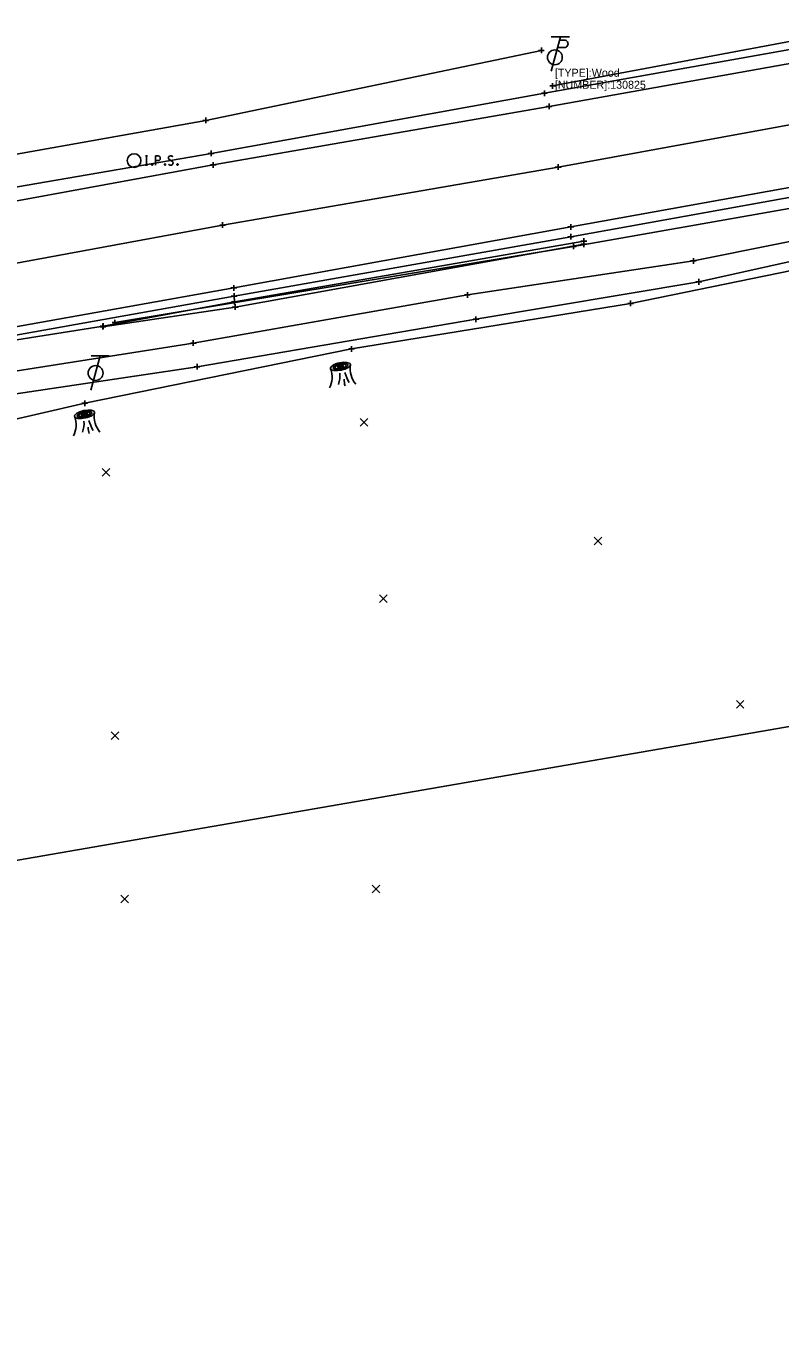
# Model space of a CAD drawing. Extents: x 1386013 to 1389776, y 604170 to 607009.
# Drawn here: x 1387481.7 to 1387613.6, y 604637.2 to 604864.4 of the extents above; entities that cross this region are included whole.
import ezdxf

# ---------------------------------------------------------------- set-up
doc = ezdxf.new("R2010")
doc.units = 0
for name, color, linetype in [('_CIVIL_CONSTRUCTION', 7, 'Continuous'), ('DV_X_Text', 7, 'Continuous'), ('PM_X_CL_Double_Solid', 7, 'Continuous'), ('PV_X_COP', 7, 'Continuous'), ('PV_X_EOP', 7, 'Continuous'), ('PV_X_Shoulder', 7, 'Continuous'), ('PV_X_Shoulder_Aggregate', 7, 'Continuous'), ('RD_X_GR_Lt', 7, 'Continuous'), ('RD_X_GR_Rt', 7, 'Continuous'), ('SC_Scratch13', 7, 'Continuous'), ('SH_Cut_Line', 7, 'Continuous'), ('SV_P_Mon_Cells_Set', 7, 'Continuous'), ('SV_X_Random_Point', 7, 'Continuous'), ('SV_X_Text', 7, 'Continuous'), ('SV_X_Toe_of_Slope', 7, 'Continuous'), ('SV_X_Top_of_Bank', 7, 'Continuous'), ('UT_X_Telecom_Cells', 7, 'Continuous')]:
    doc.layers.add(name, color=color, linetype=linetype)

msp = doc.modelspace()

# ---------------------------------------------------------------- linework, layer by layer
at = {"layer": '_CIVIL_CONSTRUCTION'}
for p, q in [((1387537.11, 604803.34), (1387537.11, 604803.34)), ((1387492.34, 604794.97), (1387492.34, 604794.97))]:
    msp.add_line(p, q, dxfattribs=at)
for centre, radius, start, end in [((1387542.72, 604804.48), 4.29, 171.4106, 219.9194), ((1387531.28, 604802.99), 4, 331.5338, 20.9269), ((1387531.6, 604803.37), 5.05, 340.7938, 3.5481), ((1387543.62, 604805.4), 6.32, 194.9653, 212.1216), ((1387541.02, 604802.54), 3.64, 178.7926, 197.1224), ((1387486.5, 604794.62), 4, 331.5338, 20.9269), ((1387497.94, 604796.11), 4.29, 171.4106, 219.9194), ((1387486.82, 604794.99), 5.05, 340.7938, 3.5481), ((1387496.24, 604794.17), 3.64, 178.7926, 197.1224), ((1387498.84, 604797.02), 6.32, 194.9653, 212.1216)]:
    msp.add_arc(centre, radius, start, end, dxfattribs=at)
for centre, major_axis in [((1387536.74, 604804.85), (1.74, 0.37)), ((1387536.74, 604804.85), (1.3, 0.28)), ((1387536.74, 604804.85), (0.976, 0.211)), ((1387536.74, 604804.85), (0.549, 0.119)), ((1387536.74, 604804.85), (0.309, 0.067)), ((1387491.96, 604796.48), (1.74, 0.37)), ((1387491.96, 604796.48), (1.3, 0.28)), ((1387491.96, 604796.48), (0.976, 0.211)), ((1387491.96, 604796.48), (0.549, 0.119)), ((1387491.96, 604796.48), (0.309, 0.067))]:
    msp.add_ellipse(centre, major_axis=major_axis, ratio=0.36865, dxfattribs=at)
at = {"layer": 'DV_X_Text'}
for p, q in [((1387571.4, 604860.13), (1387572.4, 604860.13)), ((1387571.9, 604860.63), (1387571.9, 604859.63)), ((1387571.9, 604860.13), (1387571.9, 604860.13)), ((1387572.42, 604853.14), (1387572.42, 604852.14)), ((1387573.36, 604853.92), (1387574.36, 604853.92)), ((1387573.86, 604854.42), (1387573.86, 604853.42)), ((1387573.86, 604853.92), (1387573.86, 604853.92)), ((1387571.92, 604852.64), (1387572.92, 604852.64)), ((1387572.42, 604852.64), (1387572.42, 604852.64)), ((1387573.23, 604850.83), (1387573.23, 604849.83)), ((1387513.17, 604848.4), (1387513.17, 604847.4)), ((1387572.73, 604850.33), (1387573.73, 604850.33)), ((1387573.23, 604850.33), (1387573.23, 604850.33)), ((1387512.67, 604847.9), (1387513.67, 604847.9)), ((1387513.17, 604847.9), (1387513.17, 604847.9)), ((1387513.6, 604842.11), (1387514.6, 604842.11)), ((1387514.1, 604842.61), (1387514.1, 604841.61)), ((1387514.1, 604842.11), (1387514.1, 604842.11)), ((1387513.98, 604840.1), (1387514.98, 604840.1)), ((1387514.48, 604840.6), (1387514.48, 604839.6)), ((1387514.48, 604840.1), (1387514.48, 604840.1)), ((1387574.32, 604839.73), (1387575.32, 604839.73)), ((1387574.82, 604840.23), (1387574.82, 604839.23)), ((1387574.82, 604839.73), (1387574.82, 604839.73)), ((1387516.12, 604830.08), (1387516.12, 604829.08)), ((1387515.62, 604829.58), (1387516.62, 604829.58)), ((1387516.12, 604829.58), (1387516.12, 604829.58)), ((1387576.54, 604829.26), (1387577.54, 604829.26)), ((1387577.02, 604828.03), (1387577.02, 604827.03)), ((1387577.04, 604829.76), (1387577.04, 604828.76)), ((1387577.04, 604829.26), (1387577.04, 604829.26)), ((1387576.52, 604827.53), (1387577.52, 604827.53)), ((1387577, 604825.85), (1387578, 604825.85)), ((1387577.02, 604827.53), (1387577.02, 604827.53)), ((1387577.5, 604826.35), (1387577.5, 604825.35)), ((1387577.5, 604825.85), (1387577.5, 604825.85)), ((1387578.79, 604826.22), (1387579.79, 604826.22)), ((1387578.81, 604826.78), (1387579.81, 604826.78)), ((1387579.29, 604826.72), (1387579.29, 604825.72)), ((1387579.29, 604826.22), (1387579.29, 604826.22)), ((1387579.31, 604827.28), (1387579.31, 604826.28)), ((1387579.31, 604826.78), (1387579.31, 604826.78)), ((1387597.98, 604823.3), (1387598.98, 604823.3)), ((1387598.48, 604823.8), (1387598.48, 604822.8)), ((1387598.48, 604823.3), (1387598.48, 604823.3)), ((1387518.08, 604819.08), (1387518.08, 604818.08)), ((1387598.93, 604819.65), (1387599.93, 604819.65)), ((1387599.43, 604820.15), (1387599.43, 604819.15)), ((1387599.43, 604819.65), (1387599.43, 604819.65)), ((1387517.58, 604818.58), (1387518.58, 604818.58)), ((1387517.62, 604817.16), (1387518.62, 604817.16)), ((1387518.08, 604818.58), (1387518.08, 604818.58)), ((1387518.12, 604817.66), (1387518.12, 604816.66)), ((1387518.12, 604817.16), (1387518.12, 604817.16)), ((1387518.18, 604816.66), (1387518.18, 604815.66)), ((1387558.45, 604817.37), (1387559.45, 604817.37)), ((1387558.95, 604817.87), (1387558.95, 604816.87)), ((1387558.95, 604817.37), (1387558.95, 604817.37)), ((1387517.68, 604816.16), (1387518.68, 604816.16)), ((1387517.81, 604815.24), (1387518.81, 604815.24)), ((1387518.18, 604816.16), (1387518.18, 604816.16)), ((1387518.31, 604815.74), (1387518.31, 604814.74)), ((1387518.31, 604815.24), (1387518.31, 604815.24)), ((1387587, 604815.89), (1387588, 604815.89)), ((1387587.5, 604816.39), (1387587.5, 604815.39)), ((1387587.5, 604815.89), (1387587.5, 604815.89)), ((1387494.71, 604811.9), (1387495.71, 604811.9)), ((1387495.16, 604812.31), (1387495.16, 604811.31)), ((1387495.21, 604812.4), (1387495.21, 604811.4)), ((1387495.21, 604811.9), (1387495.21, 604811.9)), ((1387496.77, 604812.51), (1387497.77, 604812.51)), ((1387497.27, 604813.01), (1387497.27, 604812.01)), ((1387497.27, 604812.51), (1387497.27, 604812.51)), ((1387559.94, 604813.11), (1387560.94, 604813.11)), ((1387560.44, 604813.61), (1387560.44, 604812.61)), ((1387560.44, 604813.11), (1387560.44, 604813.11)), ((1387494.66, 604811.81), (1387495.66, 604811.81)), ((1387495.16, 604811.81), (1387495.16, 604811.81)), ((1387510.49, 604808.94), (1387511.49, 604808.94)), ((1387510.99, 604809.44), (1387510.99, 604808.44)), ((1387510.99, 604808.94), (1387510.99, 604808.94)), ((1387538.19, 604807.91), (1387539.19, 604807.91)), ((1387538.69, 604808.41), (1387538.69, 604807.41)), ((1387538.69, 604807.91), (1387538.69, 604807.91)), ((1387511.64, 604805.29), (1387511.64, 604804.29)), ((1387511.14, 604804.79), (1387512.14, 604804.79)), ((1387511.64, 604804.79), (1387511.64, 604804.79)), ((1387491.5, 604798.41), (1387492.5, 604798.41)), ((1387492, 604798.91), (1387492, 604797.91)), ((1387492, 604798.41), (1387492, 604798.41))]:
    msp.add_line(p, q, dxfattribs=at)
at = {"layer": 'PM_X_CL_Double_Solid'}
msp.add_lwpolyline([(1386941.92, 604730.57), (1387000.37, 604739.9), (1387059.38, 604750.41), (1387127.32, 604761.93), (1387175.52, 604769.9), (1387233.31, 604779.13), (1387291.85, 604789.88), (1387343.04, 604798.39), (1387403.9, 604809.05), (1387458.49, 604818.93), (1387516.12, 604829.58), (1387574.82, 604839.73), (1387636.99, 604851.11), (1387704.35, 604863.01), (1387787.5, 604877.74), (1387859.73, 604890.76), (1387934.47, 604903.86), (1387998.85, 604914.97), (1388072.27, 604927.44)], dxfattribs=at)
at = {"layer": 'PV_X_COP'}
msp.add_lwpolyline([(1388072.27, 604927.44), (1387998.85, 604914.97), (1387934.47, 604903.86), (1387859.73, 604890.76), (1387787.5, 604877.74), (1387704.35, 604863.01), (1387636.99, 604851.11), (1387574.82, 604839.73), (1387516.12, 604829.58), (1387458.49, 604818.93), (1387403.9, 604809.05), (1387343.04, 604798.39), (1387291.85, 604789.88), (1387233.31, 604779.13), (1387175.52, 604769.9), (1387127.32, 604761.93), (1387059.38, 604750.41), (1387000.37, 604739.9), (1386941.92, 604730.57)], dxfattribs=at)
at = {"layer": 'PV_X_EOP'}
for points in [[(1388070.9, 604937.92), (1387997.67, 604925.46), (1387932.45, 604914.15), (1387857.85, 604900.92), (1387785.1, 604888.09), (1387704.04, 604873.65), (1387634.94, 604861.37), (1387573.23, 604850.33), (1387514.48, 604840.1), (1387457.17, 604829.65), (1387402.44, 604819.9), (1387341.38, 604808.9), (1387290.36, 604800.04), (1387231.98, 604789.91), (1387174.35, 604780.15), (1387125.76, 604771.91), (1387057.82, 604760.3), (1386999.09, 604750.97), (1386941.41, 604741.04)], [(1388073.48, 604916.74), (1388000.2, 604904.18), (1387936.61, 604893.17), (1387861, 604879.89), (1387788.15, 604866.91), (1387706.18, 604852.38), (1387637.62, 604840.16), (1387577.04, 604829.26), (1387518.08, 604818.58), (1387459.96, 604808.24), (1387405.36, 604798.5), (1387345.11, 604787.75), (1387291.8, 604778.43), (1387234.86, 604768.47), (1387177.43, 604758.7), (1387129.4, 604750.56), (1387061.72, 604739.2), (1387002.9, 604729.17), (1386943.42, 604719.4)]]:
    msp.add_lwpolyline(points, dxfattribs=at)
at = {"layer": 'PV_X_Shoulder'}
for points in [[(1388070.88, 604939.75), (1387997.08, 604927.24), (1387932.1, 604916.23), (1387857.34, 604902.99), (1387785.16, 604890.04), (1387703.39, 604875.43), (1387634.35, 604863.66), (1387572.42, 604852.64), (1387514.1, 604842.11), (1387456.78, 604832.26), (1387401.91, 604822.43), (1387340.63, 604811.34), (1387290.11, 604802.67), (1387231.45, 604791.93), (1387174.18, 604782.71), (1387125.33, 604774.1), (1387057.54, 604762.26), (1386998.59, 604752.7), (1386940.97, 604743.32)], [(1388073.66, 604915.38), (1388000.63, 604902.69), (1387936.79, 604891.84), (1387860.98, 604878.42), (1387788.19, 604865.06), (1387706.38, 604850.4), (1387637.88, 604838.5), (1387577.02, 604827.53), (1387518.12, 604817.16), (1387460.26, 604806.85), (1387405.51, 604796.97), (1387345.32, 604786.5), (1387292.14, 604776.93), (1387235.04, 604767.03), (1387177.5, 604757.13), (1387129.28, 604748.59), (1387117.65, 604744.89), (1387099.29, 604741.91), (1387094.7, 604743.05), (1387062.03, 604737.87), (1387002.75, 604727.47), (1386990.61, 604725.25), (1386985.4, 604722.84), (1386965.11, 604719.46)]]:
    msp.add_lwpolyline(points, dxfattribs=at)
at = {"layer": 'PV_X_Shoulder_Aggregate'}
msp.add_lwpolyline([(1387579.29, 604826.22), (1387518.31, 604815.24), (1387495.16, 604811.81)], dxfattribs=at)
at = {"layer": 'RD_X_GR_Lt'}
msp.add_lwpolyline([(1387771.56, 604860.72), (1387706.42, 604849.12), (1387638.74, 604836.61), (1387577.5, 604825.85), (1387497.27, 604812.51)], dxfattribs=at)
at = {"layer": 'RD_X_GR_Rt'}
msp.add_lwpolyline([(1387774.57, 604889.52), (1387703.04, 604877.37), (1387633.65, 604865.16), (1387573.86, 604853.92)], dxfattribs=at)
at = {"layer": 'SC_Scratch13'}
for points in [[(1387502.63, 604841.67), (1387502.99, 604841.67)], [(1387502.81, 604840.07), (1387502.81, 604841.67)], [(1387504.38, 604840.07), (1387504.38, 604841.67), (1387504.9, 604841.67), (1387504.96, 604841.66), (1387505.04, 604841.63), (1387505.07, 604841.61), (1387505.1, 604841.58), (1387505.15, 604841.52), (1387505.18, 604841.45), (1387505.2, 604841.35), (1387505.2, 604841.2), (1387505.19, 604841.15), (1387505.17, 604841.08), (1387505.13, 604840.99), (1387505.08, 604840.95), (1387505.05, 604840.93), (1387504.99, 604840.9), (1387504.9, 604840.89), (1387504.38, 604840.89)], [(1387507.38, 604841.56), (1387507.36, 604841.58), (1387507.33, 604841.61), (1387507.23, 604841.64), (1387507.11, 604841.67), (1387507.02, 604841.67), (1387506.99, 604841.67), (1387506.84, 604841.63), (1387506.72, 604841.56), (1387506.65, 604841.45), (1387506.62, 604841.35), (1387506.62, 604841.28), (1387506.65, 604841.18), (1387506.73, 604841.09), (1387507.34, 604840.71), (1387507.4, 604840.66), (1387507.42, 604840.61), (1387507.44, 604840.53), (1387507.44, 604840.46), (1387507.43, 604840.38), (1387507.42, 604840.33), (1387507.4, 604840.27), (1387507.37, 604840.22), (1387507.35, 604840.18), (1387507.32, 604840.14), (1387507.29, 604840.12), (1387507.24, 604840.09), (1387507.21, 604840.08), (1387507.11, 604840.07), (1387506.95, 604840.07), (1387506.86, 604840.09), (1387506.71, 604840.18), (1387506.62, 604840.26)], [(1387502.63, 604840.07), (1387502.99, 604840.07)], [(1387503.77, 604840.28), (1387503.82, 604840.28), (1387503.86, 604840.26), (1387503.89, 604840.21), (1387503.89, 604840.14), (1387503.86, 604840.09), (1387503.82, 604840.07), (1387503.77, 604840.07), (1387503.74, 604840.09), (1387503.7, 604840.14), (1387503.7, 604840.21), (1387503.74, 604840.26), (1387503.77, 604840.28)], [(1387506.02, 604840.28), (1387506.07, 604840.28), (1387506.11, 604840.26), (1387506.14, 604840.21), (1387506.14, 604840.14), (1387506.11, 604840.09), (1387506.07, 604840.07), (1387506.02, 604840.07), (1387505.98, 604840.09), (1387505.95, 604840.14), (1387505.95, 604840.21), (1387505.98, 604840.26), (1387506.02, 604840.28)], [(1387508.2, 604840.28), (1387508.26, 604840.28), (1387508.29, 604840.26), (1387508.32, 604840.21), (1387508.32, 604840.14), (1387508.29, 604840.09), (1387508.26, 604840.07), (1387508.2, 604840.07), (1387508.17, 604840.09), (1387508.13, 604840.14), (1387508.13, 604840.21), (1387508.17, 604840.26), (1387508.2, 604840.28)]]:
    msp.add_lwpolyline(points, dxfattribs=at)
msp.add_circle((1387500.62, 604840.87), 1.2, dxfattribs=at)
at = {"layer": 'SH_Cut_Line'}
msp.add_lwpolyline([(1387387.31, 604702.37), (1387349.76, 604919.15), (1387684.77, 604977.18), (1387722.32, 604760.41)], close=True, dxfattribs=at)
at = {"layer": 'SV_P_Mon_Cells_Set'}
for p, q in [((1387575.21, 604862.53), (1387573.6, 604856.53)), ((1387576.81, 604862.53), (1387573.61, 604862.53)), ((1387575.05, 604861.93), (1387575.9, 604861.93)), ((1387574.71, 604860.66), (1387575.9, 604860.66))]:
    msp.add_line(p, q, dxfattribs=at)
msp.add_circle((1387574.25, 604858.93), 1.3, dxfattribs=at)
msp.add_arc((1387575.91, 604861.29), 0.638, 268.8767, 91.1233, dxfattribs=at)
at = {"layer": 'SV_X_Random_Point'}
for p, q in [((1387540.21, 604794.4), (1387541.54, 604795.73)), ((1387540.21, 604795.73), (1387541.54, 604794.4)), ((1387495.04, 604785.64), (1387496.37, 604786.97)), ((1387495.04, 604786.97), (1387496.37, 604785.64)), ((1387581.13, 604773.66), (1387582.46, 604774.99)), ((1387581.13, 604774.99), (1387582.46, 604773.66)), ((1387543.55, 604763.57), (1387544.88, 604764.91)), ((1387543.55, 604764.91), (1387544.88, 604763.57)), ((1387606, 604745.06), (1387607.33, 604746.39)), ((1387606, 604746.39), (1387607.33, 604745.06)), ((1387496.59, 604739.58), (1387497.93, 604740.91)), ((1387496.59, 604740.91), (1387497.93, 604739.58)), ((1387498.3, 604711), (1387499.63, 604712.34)), ((1387498.3, 604712.34), (1387499.63, 604711)), ((1387542.31, 604712.76), (1387543.64, 604714.1)), ((1387542.31, 604714.1), (1387543.64, 604712.76))]:
    msp.add_line(p, q, dxfattribs=at)
at = {"layer": 'SV_X_Toe_of_Slope'}
for points in [[(1387571.9, 604860.13), (1387513.17, 604847.9), (1387455.73, 604837.69), (1387401.04, 604827.65), (1387339.29, 604815.83), (1387289.1, 604807.74), (1387230.03, 604798.15), (1387173.08, 604787.71), (1387123.84, 604780.19), (1387058.58, 604768.72), (1386997.09, 604757.11), (1386939.93, 604748.73), (1386883.98, 604739), (1386826.09, 604728.82), (1386769.04, 604719.03), (1386711.7, 604710.77), (1386654.03, 604700.72), (1386592.6, 604690.63), (1386534.1, 604681.18), (1386480.03, 604672.89), (1386465.51, 604671.66), (1386391.46, 604656.56), (1386330.8, 604647.36), (1386266.18, 604637.16)], [(1387642.64, 604832.21), (1387598.48, 604823.3), (1387558.95, 604817.37), (1387510.99, 604808.94), (1387471.62, 604802.75), (1387417.67, 604793.63), (1387365.33, 604784.07), (1387322.85, 604775.64), (1387270.33, 604764.8), (1387223.53, 604756.91), (1387181.6, 604750.67), (1387155.52, 604744), (1387129.15, 604740.81), (1387125.03, 604741.78), (1387120.43, 604741.02)], [(1387645.49, 604830.06), (1387640.63, 604828.81), (1387599.43, 604819.65), (1387560.44, 604813.11), (1387511.64, 604804.79), (1387472.9, 604799.01), (1387418.9, 604788.91), (1387366.41, 604779.89), (1387324.47, 604770.63), (1387271.89, 604759.84), (1387225.55, 604751.97), (1387182.66, 604746.29), (1387156.28, 604739.69), (1387120.85, 604736.53)]]:
    msp.add_lwpolyline(points, dxfattribs=at)
at = {"layer": 'SV_X_Top_of_Bank'}
for points in [[(1387579.31, 604826.78), (1387518.18, 604816.16), (1387495.21, 604811.9), (1387460.53, 604806.4), (1387405.65, 604795.75), (1387345.73, 604785.65), (1387292.4, 604775.68), (1387235, 604765.96), (1387177.62, 604755.88), (1387129.66, 604747.3), (1387125.36, 604745.57), (1387119.56, 604742.59), (1387120.12, 604734.17)], [(1387120.44, 604732.56), (1387162.47, 604738.46), (1387215.74, 604745.53), (1387273.8, 604754.33), (1387315.9, 604762.49), (1387378.29, 604774.45), (1387445.09, 604787.58), (1387492, 604798.41), (1387538.69, 604807.91), (1387587.5, 604815.89), (1387625.32, 604823.63), (1387642.48, 604825.61)]]:
    msp.add_lwpolyline(points, dxfattribs=at)
at = {"layer": 'UT_X_Telecom_Cells'}
for p, q in [((1387494.69, 604806.7), (1387493.08, 604800.7)), ((1387496.29, 604806.7), (1387493.09, 604806.7))]:
    msp.add_line(p, q, dxfattribs=at)
msp.add_circle((1387493.89, 604803.7), 1.3, dxfattribs=at)

# ---------------------------------------------------------------- texts
at = {"layer": 'SV_X_Text'}
for s, p in [('[TYPE]:Wood', (1387574.25, 604855.53)), ('[NUMBER]:130825', (1387574.25, 604853.43))]:
    msp.add_text(s, height=1.4, dxfattribs=at).set_placement(p)

doc.saveas('drawing.dxf')
